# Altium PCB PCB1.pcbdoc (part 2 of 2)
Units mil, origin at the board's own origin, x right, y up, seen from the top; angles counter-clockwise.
Board outline 3270 x 3720 mil, 2 copper layers (Top Layer, Bottom Layer); 54 components, 39 nets, 206 pads, 56 vias.
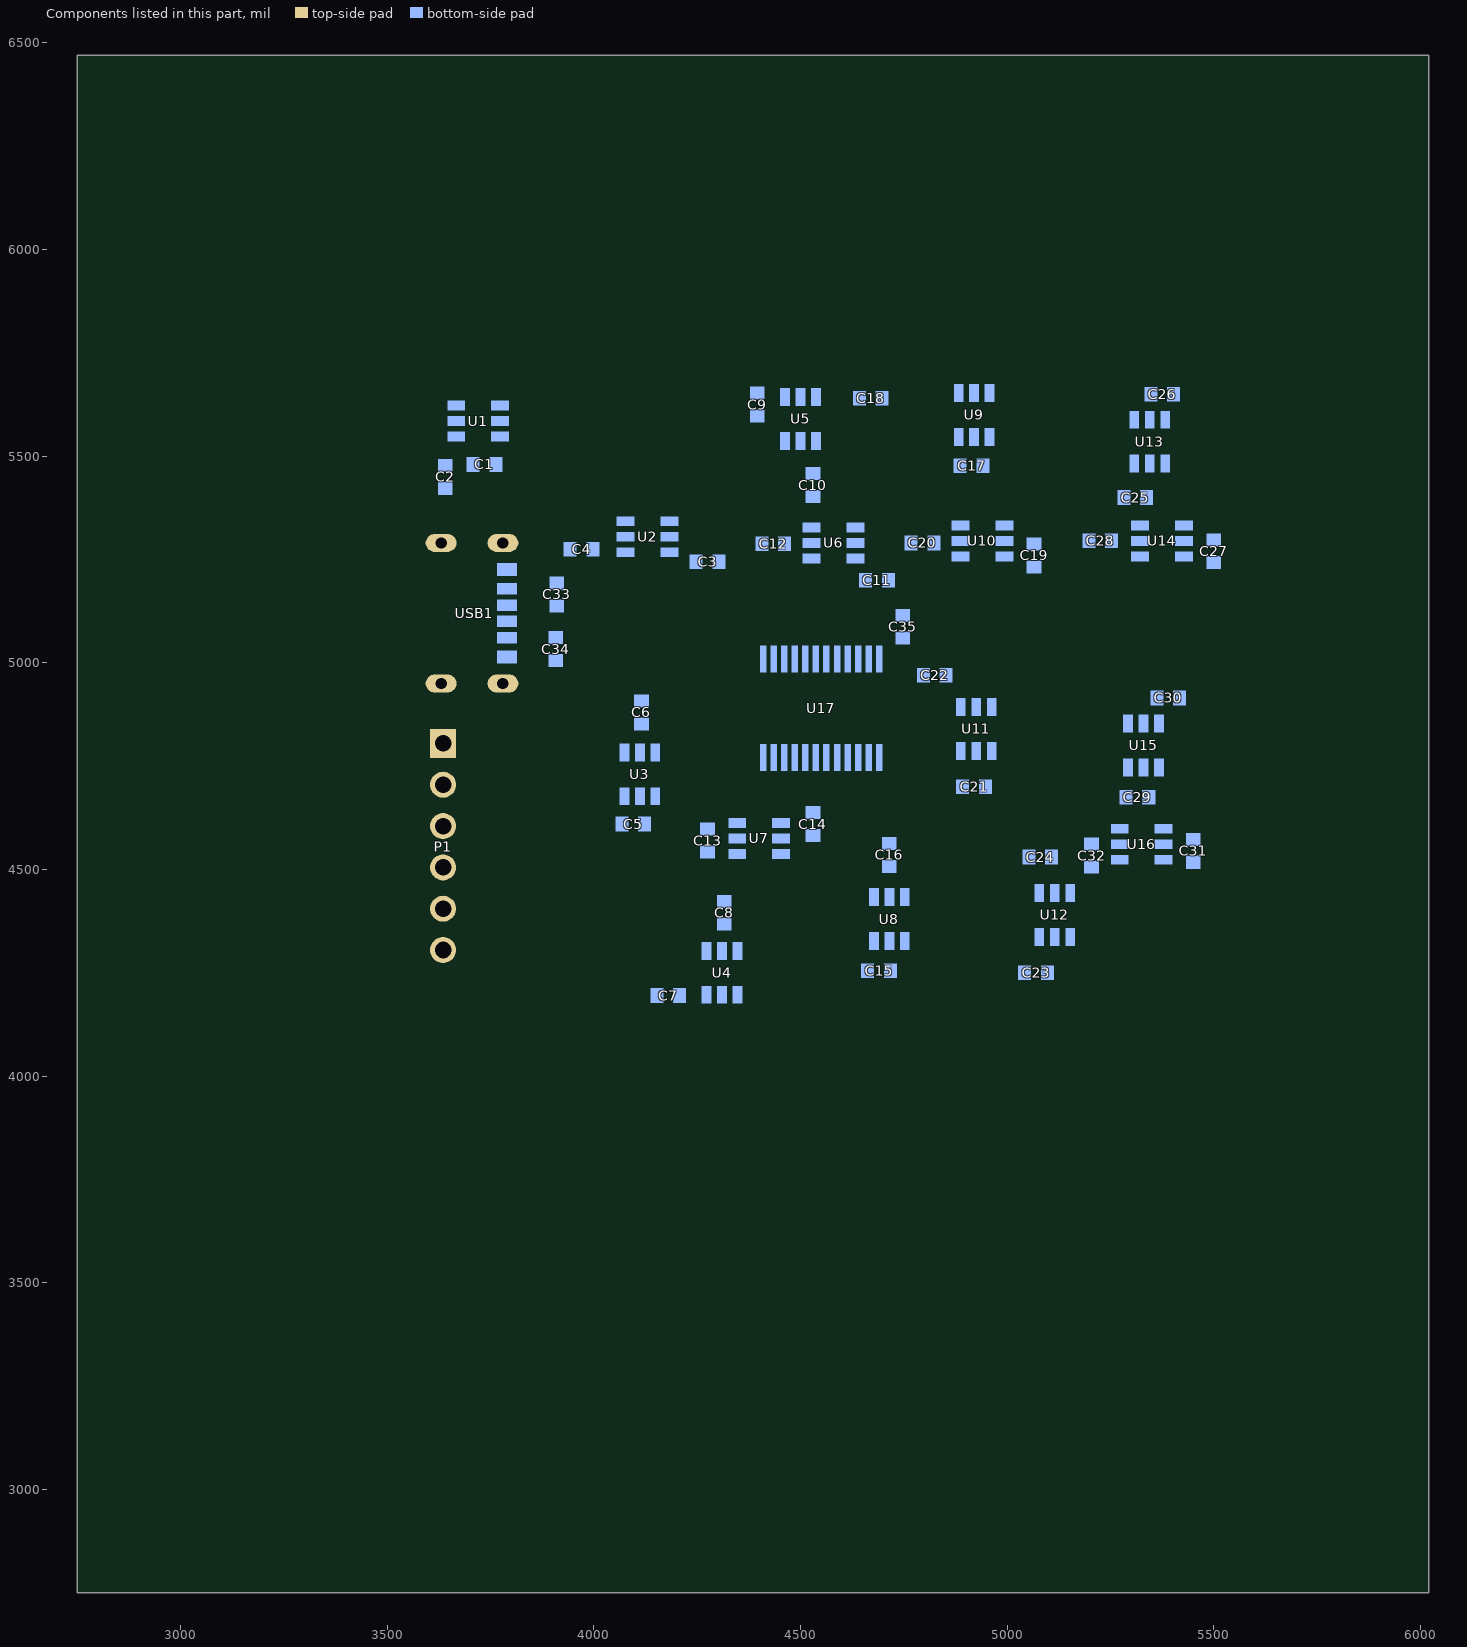
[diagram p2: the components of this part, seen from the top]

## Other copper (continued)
Bottom Layer:
  region net GND: 3702.44,5512.72 3712.44,5512.72 ccw(c3731.19,5512.72) 3719.94,5497.72 3694.94,5497.72 ccw(c3683.69,5512.72)
  region net GND: 3676.69,5472.56 3676.69,5482.56 ccw(c3676.69,5501.31) 3691.69,5490.06 3691.69,5465.06 ccw(c3676.69,5453.81)
  region: 3768.15,5512.72 3778.15,5512.72 ccw(c4490.25,5512.72) 3778.31,5497.72 3760.65,5497.72 ccw(c3749.4,5512.72)
  region: 3754.05,5456.98 3746.46,5463.54 ccw(c3574,5474.49) 3746.81,5474.49 3769.96,5462.28 ccw(c3769.96,5435.77)
  region net GND: 3672.72,5482.56 3672.72,5472.56 ccw(c3672.72,5453.81) 3657.72,5465.06 3657.72,5490.06 ccw(c3672.72,5501.31)
  region net +5V: 3663.02,5406.49 3653.98,5401.39 ccw(c3638.07,5380.18) 3638.07,5406.69 3657.72,5422.4 ccw(c3684.23,5422.4)
  region net +5V: 3616.98,5438.39 3626.02,5443.49 ccw(c3641.93,5464.7) 3641.93,5438.19 3622.28,5422.48 ccw(c3595.77,5422.48)
  region net PAD2: 4226.39,5258.98 4231.49,5268.02 ccw(c4247.4,5289.23) 4247.4,5262.72 4231.69,5243.07 ccw(c4205.18,5243.07)
  region net +5V: 4002.56,5242.28 3992.56,5242.28 ccw(c3973.81,5242.28) 3985.06,5257.28 4010.06,5257.28 ccw(c4021.31,5242.28)
  region net +5V: 4013.51,5298.02 4018.61,5288.98 ccw(c4039.82,5273.07) 4013.31,5273.07 3997.6,5292.72 ccw(c3997.6,5319.23)
  region net GND: 4106.3,4642.72 4116.3,4642.72 ccw(c4135.05,4642.72) 4123.8,4627.72 4106.81,4627.72 ccw(c3888.95,4627.72)
  region net PAD3: 4053.54,4589.02 4046.46,4596.1 ccw(c4025.1,4611.93) 4051.69,4611.93 4067.4,4592.28 ccw(c4067.4,4561.16)
  region net PAD3: 4062.44,4642.72 4072.44,4642.72 ccw(c4091.19,4642.72) 4079.94,4627.72 4054.94,4627.72 ccw(c4043.69,4642.72)
  region net +5V: 4120,4821.69 4110,4821.69 ccw(c4091.25,4821.69) 4102.5,4836.69 4127.5,4836.69 ccw(c4138.75,4821.69)
  region net +5V: 4141.46,4868.54 4138.85,4851.78 ccw(c4154.34,4836.69) 4132.72,4836.69 4132.72,4868.19 ccw(c4136.9,4873.1)
  region net PAD4: 4238.31,4200 4238.31,4190 ccw(c4238.31,4171.25) 4223.31,4182.5 4223.31,4207.5 ccw(c4238.31,4218.75)
  region net PAD4: 4226.46,4213.54 4231.2,4204.13 ccw(c4253.28,4182.05) 4223.31,4190.81 4223.31,4212.72 ccw(c4224.19,4215.81)
  region net +5V: 4320,4336.69 4310,4336.69 ccw(c4291.25,4336.69) 4302.5,4351.69 4327.5,4351.69 ccw(c4338.75,4336.69)
  region net +5V: 4328.98,4388.49 4338.02,4383.39 ccw(c4359.23,4367.48) 4332.72,4367.48 4313.07,4383.19 ccw(c4313.07,4409.7)
  region net PAD5: 4418.02,5581.49 4408.98,5576.39 ccw(c4393.07,5555.18) 4393.07,5581.69 4412.72,5597.4 ccw(c4439.23,5597.4)
  region net PAD5: 4371.98,5613.39 4381.02,5618.49 ccw(c4396.93,5639.7) 4396.93,5613.19 4377.28,5597.48 ccw(c4350.77,5597.48)
  region net +5V: 4553.02,5441.61 4543.98,5436.51 ccw(c4528.07,5415.3) 4528.07,5441.81 4547.72,5457.52 ccw(c4574.23,5457.52)
  region net +5V: 4543.98,5478.61 4553.02,5473.51 ccw(c4574.23,5457.6) 4547.72,5457.6 4528.07,5473.31 ccw(c4528.07,5499.82)
  region net +5V: 4492.4,5293.47 4492.4,5283.47 ccw(c4492.4,5264.72) 4477.4,5275.97 4477.4,5300.97 ccw(c4492.4,5312.22)
  region net GND: 4302.69,4547.44 4302.69,4537.44 ccw(c4302.69,4527.06) 4292.72,4529.94 4292.72,4554.94 ccw(c4302.69,4557.82)
  region net PAD7: 4250,4580 4250,4590 ccw(c4249.78,4597.5) 4257.28,4597.5 4257.28,4581.81 ccw(c4257.28,4566.27)
  region net PAD7: 4307.72,4602.56 4307.72,4592.56 ccw(c4307.72,4573.81) 4292.72,4585.06 4292.72,4610.06 ccw(c4307.72,4621.31)
  region net +5V: 4516.02,4616.51 4506.98,4621.61 ccw(c4485.77,4637.52) 4512.28,4637.52 4531.93,4621.81 ccw(c4531.93,4595.3)
  region net +5V: 4562.72,4642.56 4562.72,4632.56 ccw(c4562.72,4613.81) 4547.72,4625.06 4547.72,4650.06 ccw(c4562.72,4661.31)
  region net PAD8: 4663.16,4231.09 4646.46,4228.54 ccw(c4641.97,4233.03) 4646.69,4237.28 4678.19,4237.28 ccw(c4678.19,4215.96)
  region net PAD8: 4672.6,4287.72 4682.6,4287.72 ccw(c4705.89,4272.72) 4678.19,4272.72 4665.1,4272.72 ccw(c4653.85,4287.72)
  region net +5V: 4720,4476.69 4710,4476.69 ccw(c4691.25,4476.69) 4702.5,4491.69 4727.5,4491.69 ccw(c4738.75,4476.69)
  region net +5V: 4691.98,4523.39 4701.02,4528.49 ccw(c4716.93,4549.7) 4716.93,4523.19 4697.28,4507.48 ccw(c4670.77,4507.48)
  region net +5V: 4681.61,5616.98 4676.51,5626.02 ccw(c4655.3,5641.93) 4681.81,5641.93 4697.52,5622.28 ccw(c4697.52,5595.77)
  region net +5V: 4728.31,5655 4728.31,5645 ccw(c4728.31,5626.25) 4713.31,5637.5 4713.31,5657.72 ccw(c4728.31,5697.77)
  region net PAD10: 5041.98,5248.39 5051.02,5253.49 ccw(c5066.93,5274.7) 5066.93,5248.19 5047.28,5232.48 ccw(c5020.77,5232.48)
  region net PAD10: 5088.91,5233.16 5096.46,5211.46 ccw(c5083.77,5198.77) 5082.72,5216.69 5082.72,5248.19 ccw(c5104.04,5248.19)
  region net +5V: 4814.05,5266.98 4806.46,5273.54 ccw(c4634,5284.49) 4806.81,5284.49 4829.96,5272.28 ccw(c4829.96,5245.77)
  region net +5V: 4853.31,5295 4853.31,5285 ccw(c4853.31,5266.25) 4838.31,5277.5 4838.31,5302.5 ccw(c4853.31,5313.75)
  region net PAD11: 4897.44,4667.28 4887.44,4667.28 ccw(c4868.69,4667.28) 4879.94,4682.28 4904.94,4682.28 ccw(c4916.19,4667.28)
  region net PAD11: 4887.44,4732.72 4897.44,4732.72 ccw(c4916.19,4732.72) 4904.94,4717.72 4879.94,4717.72 ccw(c4868.69,4732.72)
  region net +5V: 4831.51,4983.98 4836.61,4993.02 ccw(c4852.52,5014.23) 4852.52,4987.72 4836.81,4968.07 ccw(c4810.3,4968.07)
  region net +5V: 4883.31,4960 4883.31,4950 ccw(c4868.31,4901.88) 4868.31,4952.28 4868.31,4967.5 ccw(c4883.31,4978.75)
  region net PAD12: 5047.44,4227.44 5037.44,4227.44 ccw(c5029.94,4224.06) 5029.94,4232.28 5054.94,4232.28 ccw(c5054.94,4224.06)
  region net PAD12: 5058.39,4273.02 5063.49,4263.98 ccw(c5084.7,4248.07) 5058.19,4248.07 5042.48,4267.72 ccw(c5042.48,4294.23)
  region net +5V: 5123.51,4553.02 5128.61,4543.98 ccw(c5149.82,4528.07) 5123.31,4528.07 5107.6,4547.72 ccw(c5107.6,4574.23)
  region net +5V: 5128.61,4516.02 5123.51,4506.98 ccw(c5107.6,4485.77) 5107.6,4512.28 5123.31,4531.93 ccw(c5149.82,4531.93)
  region net PAD13: 5298.39,5423.02 5303.49,5413.98 ccw(c5324.7,5398.07) 5298.19,5398.07 5282.48,5417.72 ccw(c5282.48,5444.23)
  region net +5V: 5316.69,5645 5316.69,5655 ccw(c5316.69,5673.75) 5331.69,5662.5 5331.69,5637.5 ccw(c5316.69,5626.25)
  region net +5V: 5350,5617.28 5340,5617.28 ccw(c5321.25,5617.28) 5332.5,5632.28 5357.5,5632.28 ccw(c5368.75,5617.28)
  region net PAD14: 5467.28,5252.6 5467.28,5262.6 ccw(c5482.28,5285.89) 5482.28,5258.19 5482.28,5245.1 ccw(c5467.28,5233.85)
  region net PAD14: 5505,5211.69 5495,5211.69 ccw(c5476.25,5211.69) 5487.5,5226.69 5512.5,5226.69 ccw(c5523.75,5211.69)
  region net +5V: 5247.56,5327.72 5257.56,5327.72 ccw(c5276.31,5327.72) 5265.06,5312.72 5240.06,5312.72 ccw(c5228.81,5327.72)
  region net +5V: 5283.31,5300 5283.31,5290 ccw(c5283.31,5271.25) 5268.31,5282.5 5268.31,5307.5 ccw(c5283.31,5318.75)
  region net PAD15: 5287.6,4707.72 5297.6,4707.72 ccw(c5320.53,4707.72) 5303.19,4692.72 5280.1,4692.72 ccw(c5268.85,4707.72)
  region net +5V: 5346.49,4891.98 5341.39,4901.02 ccw(c5320.18,4916.93) 5346.69,4916.93 5362.4,4897.28 ccw(c5362.4,4870.77)
  region net PAD16: 5417.28,4518.75 5417.28,4528.75 ccw(c5417.28,4556.34) 5432.28,4533.19 5432.28,4511.25 ccw(c5417.28,4500)
  region net PAD16: 5473.02,4501.49 5463.98,4496.39 ccw(c5448.07,4475.18) 5448.07,4501.69 5467.72,4517.4 ccw(c5494.23,4517.4)
  region net +5V: 5171.5,4556.15 5171.5,4566.15 ccw(c5171.5,4584.9) 5186.5,4573.65 5186.5,4548.65 ccw(c5171.5,4537.4)
  region net +5V: 5236.94,4566.15 5236.94,4556.15 ccw(c5236.94,4537.4) 5221.94,4548.65 5221.94,4573.65 ccw(c5236.94,4584.9)
  region net +5V: 3877.07,5133.05 3877.07,5143.05 ccw(c3877.07,5161.8) 3892.07,5150.55 3892.07,5125.55 ccw(c3877.07,5114.3)
  region net +5V: 3914.79,5107.3 3904.79,5107.3 ccw(c3886.04,5107.3) 3897.29,5122.3 3922.29,5122.3 ccw(c3933.54,5107.3)
  region net +5V: 3923.77,5159.1 3932.81,5154 ccw(c3954.02,5138.09) 3927.5,5138.09 3907.86,5153.8 ccw(c3907.86,5180.31)
  region net +5V: 3904.79,5091.48 3914.79,5091.48 ccw(c3933.54,5091.48) 3922.29,5076.48 3897.29,5076.48 ccw(c3886.04,5091.48)
  region net +5V: 4750,5040 4740,5040 ccw(c4732.5,5035.48) 4732.5,5044.23 4757.5,5044.23 ccw(c4757.5,5035.48)
  region net S3: 3601.03,4431.9 3608.1,4438.97 3609.88,4437.34 3611.58,4436.08 3613.2,4435.17 3614.76,4434.55 3616.3,4434.2 3617.82,4434.07 3619.35,4434.13 3620.91,4434.32 3627.82,4435.79 3631.95,4436.38 3634.26,4436.49 3636.75,4436.45 3603.55,4403.25 3603.51,4405.74 3603.62,4408.05 3604.21,4412.18 3605.68,4419.09 3605.87,4420.65 3605.93,4422.18 3605.8,4423.7 3605.45,4425.24 3604.83,4426.8 3603.92,4428.42 3602.66,4430.12
  region net S2: 3601.03,4531.9 3608.1,4538.97 3609.88,4537.34 3611.58,4536.08 3613.2,4535.17 3614.76,4534.55 3616.3,4534.2 3617.82,4534.07 3619.35,4534.13 3620.91,4534.32 3627.82,4535.79 3631.95,4536.38 3634.26,4536.49 3636.75,4536.45 3603.55,4503.25 3603.51,4505.74 3603.62,4508.05 3604.21,4512.18 3605.68,4519.09 3605.87,4520.65 3605.93,4522.18 3605.8,4523.7 3605.45,4525.24 3604.83,4526.8 3603.92,4528.42 3602.66,4530.12
  region net S1: 3678.04,4610 3678.04,4600 3675.63,4599.89 3673.54,4599.59 3671.75,4599.09 3670.21,4598.41 3668.87,4597.58 3667.7,4596.59 3666.66,4595.47 3665.7,4594.23 3661.85,4588.31 3659.34,4584.97 3657.79,4583.25 3656,4581.52 3656,4628.48 3657.79,4626.75 3659.34,4625.03 3661.85,4621.69 3665.7,4615.77 3666.66,4614.53 3667.7,4613.41 3668.87,4612.42 3670.21,4611.59 3671.75,4610.91 3673.54,4610.41 3675.63,4610.11
  region net S0: 3678.04,4710 3678.04,4700 3675.63,4699.89 3673.54,4699.59 3671.75,4699.09 3670.21,4698.41 3668.87,4697.58 3667.7,4696.59 3666.66,4695.47 3665.7,4694.23 3661.85,4688.31 3659.34,4684.97 3657.79,4683.25 3656,4681.52 3656,4728.48 3657.79,4726.75 3659.34,4725.03 3661.85,4721.69 3665.7,4715.77 3666.66,4714.53 3667.7,4713.41 3668.87,4712.42 3670.21,4711.59 3671.75,4710.91 3673.54,4710.41 3675.63,4710.11
  region: 3778.15,5520.79 3768.15,5520.79 ccw(c3749.4,5520.79) 3760.65,5535.79 3785.65,5535.79 ccw(c3796.9,5520.79)
  region net GND: 3736.5,5580 3736.5,5590 ccw(c3736.5,5609.92) 3751.5,5596.81 3751.5,5573.19 ccw(c3736.5,5560.08)
  region net T1: 3809.8,5627.4 3809.8,5617.4 ccw(c3809.8,5597.48) 3794.8,5610.59 3794.8,5634.21 ccw(c3809.8,5647.32)
  region net +5V: 3639.96,5567.89 3639.36,5581.43 ccw(c3622.01,5596.81) 3645.2,5596.81 3655.87,5573.19 ccw(c3655.87,5546.67)
  region net PAD2: 4207.6,5272.6 4207.6,5262.6 ccw(c4214.5,5255.79) 4204.8,5255.79 4204.8,5279.41 ccw(c4214.5,5279.41)
  region net T2: 4155,5337.4 4155,5347.4 ccw(c4154.68,5354.21) 4161.5,5354.21 4161.5,5330.59 ccw(c4154.68,5330.59)
  region net +5V: 4040.2,5300 4040.2,5310 ccw(c4040.2,5329.92) 4055.2,5316.81 4055.2,5293.19 ccw(c4040.2,5280.08)
  region net PAD3: 4072.44,4640.41 4062.44,4640.41 ccw(c3746.25,4640.41) 4062.08,4655.41 4079.94,4655.41 ccw(c4091.19,4640.41)
  region net GND: 4116.3,4640.41 4106.3,4640.41 ccw(c4086.37,4640.41) 4099.48,4655.41 4123.11,4655.41 ccw(c4136.22,4640.41)
  region net T3: 4168.4,4664.43 4172.22,4646.46 ccw(c4133.02,4607.26) 4160.51,4655.41 4160.51,4677.75 ccw(c4190.48,4686.51)
  region net +5V: 4110,4820.02 4120,4820.02 ccw(c4157.77,4820.02) 4123.11,4805.02 4102.5,4805.02 ccw(c4091.25,4820.02)
  region net PAD4: 4245.79,4190 4245.79,4200 ccw(c4245.79,4218.75) 4260.79,4207.5 4260.79,4182.5 ccw(c4245.79,4171.25)
  region net T4: 4366.46,4222.99 4367.1,4209.48 ccw(c4389.18,4187.4) 4359.21,4196.16 4359.21,4218.5 ccw(c4353.35,4236.1)
  region net +5V: 4310,4339.8 4320,4339.8 ccw(c4383.03,4339.8) 4321.81,4324.8 4302.5,4324.8 ccw(c4291.25,4339.8)
  region net PAD5: 4442.9,5542.47 4437.47,5562.04 ccw(c4459.55,5584.12) 4450.79,5554.15 4450.79,5529.15 ccw(c4420.82,5520.39)
  region net GND: 4505,5573.5 4515,5573.5 ccw(c4548.68,5558.5) 4511.81,5558.5 4497.5,5558.5 ccw(c4486.25,5573.5)
  region net T5: 4529.11,5509.89 4520.29,5515.21 ccw(c4499.07,5531.12) 4525.59,5531.12 4545.02,5515.2 ccw(c4545.02,5488.68)
  region net +5V: 4517.11,5619.96 4506.74,5616.19 ccw(c4490.83,5594.98) 4490.83,5621.5 4511.81,5635.87 ccw(c4538.33,5635.87)
  region net PAD6: 4660.98,5231.85 4645.78,5232.9 ccw(c4623.7,5210.82) 4632.46,5240.79 4654.8,5240.79 ccw(c4682.28,5253.15)
  region net PAD6: 4656.46,5263.54 4661.94,5254.87 ccw(c4679.88,5236.93) 4654.8,5240.79 4654.8,5264.41 ccw(c4655.86,5264.41)
  region net GND: 4655,5295 4655,5285 ccw(c4772.94,5278.19) 4654.8,5278.19 4654.8,5301.81 ccw(c4772.94,5301.81)
  region net T6: 4598.88,5306.99 4603.62,5325.87 ccw(c4581.67,5347.83) 4611.5,5339.21 4611.5,5315.59 ccw(c4627.9,5277.97)
  region net +5V: 4490.2,5283.47 4490.2,5293.47 ccw(c4490.2,5312.22) 4505.2,5300.97 4505.2,5278.19 ccw(c4490.2,5259.53)
  region net T7: 4372.6,4542.6 4372.6,4532.6 ccw(c4376.21,4525.79) 4368.5,4525.79 4368.5,4549.41 ccw(c4376.21,4549.41)
  region net +5V: 4477.48,4592.11 4480.11,4580.6 ccw(c4501.32,4564.69) 4474.8,4564.69 4461.57,4586.81 ccw(c4461.57,4613.33)
  region net PAD8: 4682.6,4290.2 4672.6,4290.2 ccw(c4652.68,4290.2) 4665.79,4305.2 4689.41,4305.2 ccw(c4702.52,4290.2)
  region net T8: 4776.2,4357.72 4772.1,4339.48 ccw(c4794.18,4317.4) 4764.21,4326.16 4764.21,4348.5 ccw(c4734.92,4399.01)
  region net +5V: 4710,4469.8 4720,4469.8 ccw(c4739.92,4469.8) 4726.81,4454.8 4703.19,4454.8 ccw(c4690.08,4469.8)
  region net PAD9: 4891.4,5510.2 4881.4,5510.2 ccw(c4862.65,5510.2) 4873.9,5525.2 4894.41,5525.2 ccw(c4930.29,5510.2)
  region net PAD9: 4880,5580 4890,5580 ccw(c4907.19,5580) 4894.41,5568.5 4872.5,5568.5 ccw(c4867.44,5580)
  region net T9: 4949.11,5519.89 4940.29,5525.21 ccw(c4919.07,5541.12) 4945.59,5541.12 4965.02,5525.2 ccw(c4965.02,5498.68)
  region net +5V: 4911.71,5626.19 4902.89,5631.51 ccw(c4881.67,5647.42) 4908.19,5647.42 4927.62,5631.5 ccw(c4927.62,5604.98)
  region net PAD10: 5029.8,5262.6 5029.8,5252.6 ccw(c5029.8,5232.68) 5014.8,5245.79 5014.8,5269.41 ccw(c5029.8,5282.52)
  region net +5V: 4850.2,5285 4850.2,5295 ccw(c4850.2,5313.75) 4865.2,5302.5 4865.2,5283.19 ccw(c4850.2,5221.97)
  region net PAD11: 4897.44,4750.2 4887.44,4750.2 ccw(c4868.69,4750.2) 4879.94,4765.2 4899.41,4765.2 ccw(c4955.5,4750.2)
  region net T11: 4955,4815 4965,4815 ccw(c4972.5,4816.08) 4972.5,4808.5 4950.59,4808.5 ccw(c4948.01,4815)
  region net +5V: 4930,4865 4920,4865 ccw(c4913.19,4864.68) 4913.19,4871.5 4936.81,4871.5 ccw(c4936.81,4864.68)
  region net +5V: 4920,4920 4930,4920 ccw(c4936.81,4921.87) 4936.81,4914.8 4913.19,4914.8 ccw(c4913.19,4921.87)
  region net PAD12: 5082.6,4300.2 5072.6,4300.2 ccw(c5052.68,4300.2) 5065.79,4315.2 5089.41,4315.2 ccw(c5102.52,4300.2)
  region net T12: 5131.9,4371.03 5150.78,4366.29 ccw(c5172.13,4387.63) 5164.21,4358.5 5140.59,4358.5 ccw(c5101.62,4340.74)
  region net PAD13: 5312.6,5445.2 5302.6,5445.2 ccw(c5282.68,5445.2) 5295.79,5460.2 5319.41,5460.2 ccw(c5332.52,5445.2)
  region net PAD13: 5305,5518.5 5315,5518.5 ccw(c5342.71,5518.5) 5319.41,5503.5 5297.5,5503.5 ccw(c5286.25,5518.5)
  region net T13: 5387.4,5445.2 5377.4,5445.2 ccw(c5357.48,5445.2) 5370.59,5460.2 5394.21,5460.2 ccw(c5407.32,5445.2)
  region net +5V: 5340,5624.8 5350,5624.8 ccw(c5369.92,5624.8) 5356.81,5609.8 5333.19,5609.8 ccw(c5320.08,5624.8)
  region net PAD14: 5464.8,5262.6 5464.8,5252.6 ccw(c5464.8,5232.68) 5449.8,5245.79 5449.8,5269.41 ccw(c5464.8,5282.52)
  region net T14: 5401.42,5327.4 5401.42,5337.4 ccw(c5399.39,5344.21) 5406.5,5344.21 5406.5,5320.59 ccw(c5399.39,5320.59)
  region net +5V: 5285.2,5290 5285.2,5300 ccw(c5285.2,5319.92) 5300.2,5306.81 5300.2,5283.19 ccw(c5285.2,5270.08)
  region net PAD15: 5297.6,4710.2 5287.6,4710.2 ccw(c5267.68,4710.2) 5280.79,4725.2 5304.41,4725.2 ccw(c5317.52,4710.2)
  region net PAD15: 5287.6,4772.6 5297.6,4772.6 ccw(c5304.41,4776.21) 5304.41,4768.5 5280.79,4768.5 ccw(c5280.79,4776.21)
  region net +5V: 5325,4882.56 5335,4882.56 ccw(c5342.82,4882.56) 5341.81,4874.8 5318.19,4874.8 ccw(c5317.18,4882.56)
  region net +5V: 5347.11,4831.51 5338.29,4826.19 ccw(c5322.38,4804.98) 5322.38,4831.5 5341.81,4847.42 ccw(c5368.33,4847.42)
  region net PAD16: 5415.34,4528.75 5415.34,4518.75 ccw(c5415.34,4498.83) 5400.34,4511.94 5400.34,4535.56 ccw(c5415.34,4548.68)
  region net +5V: 5235.73,4556.15 5235.73,4566.15 ccw(c5235.73,4586.08) 5250.73,4572.96 5250.73,4549.34 ccw(c5235.73,4536.23)
  region net +5V: 5296.2,4578.27 5299.34,4567.27 ccw(c5320.56,4551.36) 5294.04,4551.36 5280.29,4572.96 ccw(c5280.29,4599.48)
  region net T8: 4567.79,4723.52 4557.79,4723.52 ccw(c4517.21,4723.52) 4554.92,4738.52 4570.66,4738.52 ccw(c4608.37,4723.52)
  region net T12: 4593.38,4723.52 4583.38,4723.52 ccw(c4542.8,4723.52) 4580.51,4738.52 4596.25,4738.52 ccw(c4633.96,4723.52)
  region net T16: 4618.97,4723.52 4608.97,4723.52 ccw(c4568.39,4723.52) 4606.1,4738.52 4621.84,4738.52 ccw(c4659.55,4723.52)
  region net T15: 4644.56,4723.52 4634.56,4723.52 ccw(c4593.98,4723.52) 4631.69,4738.52 4647.43,4738.52 ccw(c4685.14,4723.52)
  region net T11: 4670,4723.52 4660,4723.52 ccw(c4617.34,4723.52) 4657.28,4738.52 4673.02,4738.52 ccw(c4708.71,4723.52)
  region net OUT: 4685.74,4818.48 4695.74,4818.48 ccw(c4736.32,4818.48) 4698.61,4803.48 4682.87,4803.48 ccw(c4645.16,4818.48)
  region net T4: 4540,4723.52 4530,4723.52 ccw(c4360.24,4723.52) 4529.34,4738.52 4545.08,4738.52 ccw(c4564.67,4723.52)
  region net T3: 4491.02,4736.02 4481.02,4736.02 ccw(c4478.15,4735.62) 4478.15,4738.52 4493.89,4738.52 ccw(c4493.89,4735.62)
  region net T9: 4583.38,5056.48 4593.38,5056.48 ccw(c4633.96,5056.48) 4596.25,5041.48 4580.51,5041.48 ccw(c4542.8,5056.48)
  region net T10: 4608.97,5056.48 4618.97,5056.48 ccw(c4659.55,5056.48) 4621.84,5041.48 4606.1,5041.48 ccw(c4568.39,5056.48)
  region net T13: 4634.56,5056.48 4644.56,5056.48 ccw(c4685.14,5056.48) 4647.43,5041.48 4631.69,5041.48 ccw(c4593.98,5056.48)
  region net T14: 4660.15,5054.85 4670.15,5054.85 ccw(c4702.68,5054.85) 4673.02,5041.48 4657.28,5041.48 ccw(c4627.62,5054.85)
  region net +5V: 4685.74,5045.74 4695.74,5045.74 ccw(c4700.33,5045.74) 4698.61,5041.48 4682.87,5041.48 ccw(c4681.15,5045.74)
  region net T6: 4557.79,5056.48 4567.79,5056.48 ccw(c4608.37,5056.48) 4570.66,5041.48 4554.92,5041.48 ccw(c4517.21,5056.48)
  region net S3: 4414.26,4964.26 4404.26,4964.26 ccw(c4376.68,4964.26) 4401.39,4976.52 4417.13,4976.52 ccw(c4441.84,4964.26)
  region net S2: 4439.84,4961.52 4429.84,4961.52 ccw(c4389.26,4961.52) 4426.97,4976.52 4442.71,4976.52 ccw(c4480.42,4961.52)
  region net GND: 4465.43,4961.52 4455.43,4961.52 ccw(c4414.85,4961.52) 4452.56,4976.52 4468.3,4976.52 ccw(c4506.01,4961.52)
  region net T5: 4532.21,5052.79 4542.21,5052.79 ccw(c4565.9,5052.79) 4545.08,5041.48 4529.34,5041.48 ccw(c4508.52,5052.79)
  region net +5V: 3825,5065 3825,5055 ccw(c3825,5042.2) 3813.35,5047.5 3813.35,5072.5 ccw(c3825,5077.8)
  region net +5V: 3825.95,5184.06 3825.95,5174.06 ccw(c3825.95,5159.72) 3813.35,5166.56 3813.35,5191.56 ccw(c3825.95,5198.39)
  region net +5V: 3765.95,5174.06 3765.95,5184.06 ccw(c3588.02,5191.56) 3766.1,5191.56 3766.1,5166.56 ccw(c3588.02,5166.56)
  region: 3758.07,5475.14 3765.14,5468.07 3764.41,5467.21 3763.79,5466.24 3762.84,5464.02 3762.26,5461.65 3761.99,5459.33 3749.33,5471.99 3751.65,5472.26 3754.02,5472.84 3756.24,5473.79 3757.21,5474.41
  region net PAD2: 4199.19,5262.6 4194.7,5272.6 4197.59,5272.69 4198.94,5272.86 4200.17,5273.18 4201.24,5273.67 4202.12,5274.39 4202.75,5275.37 4203.11,5276.66 4214.3,5263.01 4210.38,5263.09 4206.75,5262.93 4203.11,5262.71
  region net PAD3: 4045,4592.56 4055,4592.56 4055.09,4591.6 4055.34,4590.91 4055.73,4590.4 4056.23,4590 4057.5,4589.23 4058.21,4588.71 4058.95,4588.01 4041.05,4588.01 4041.79,4588.71 4042.5,4589.23 4043.77,4590 4044.27,4590.4 4044.66,4590.91 4044.91,4591.6
  region net PAD4: 4221.93,4194.86 4214.86,4201.93 4215.59,4202.79 4216.21,4203.76 4217.16,4205.98 4217.74,4208.35 4218.01,4210.67 4230.67,4198.01 4228.35,4197.74 4225.98,4197.16 4223.76,4196.21 4222.79,4195.59
  region net PAD5: 4336.41,5660 4336.41,5650 4335.29,5649.91 4334.16,5649.66 4331.93,5648.77 4329.83,5647.5 4328.01,5646.05 4328.01,5663.95 4329.83,5662.5 4331.93,5661.23 4334.16,5660.34 4335.29,5660.09
  region net PAD7: 4262.44,4590 4262.44,4580 4261.49,4579.91 4260.81,4579.66 4260.32,4579.27 4259.94,4578.77 4259.21,4577.5 4258.71,4576.79 4258.01,4576.05 4258.01,4593.95 4258.71,4593.21 4259.21,4592.5 4259.94,4591.23 4260.32,4590.73 4260.81,4590.34 4261.49,4590.09
  region net PAD8: 4658.07,4240.14 4665.14,4233.07 4664.41,4232.21 4663.79,4231.24 4662.84,4229.02 4662.26,4226.65 4661.99,4224.33 4649.33,4236.99 4651.65,4237.26 4654.02,4237.84 4656.24,4238.79 4657.21,4239.41
  region net PAD9: 4888.54,5576.46 4881.46,5583.54 4882.13,5584.32 4882.57,5585.12 4882.83,5585.93 4882.96,5586.78 4883.01,5590.67 4895.67,5578.01 4891.78,5577.96 4890.93,5577.83 4890.12,5577.57 4889.32,5577.13
  region net PAD10: 5084.86,5223.07 5091.93,5230.14 5092.79,5229.41 5093.76,5228.79 5095.98,5227.84 5098.35,5227.26 5100.67,5226.99 5088.01,5214.33 5087.74,5216.65 5087.16,5219.02 5086.21,5221.24 5085.59,5222.21
  region net PAD11: 4887.44,4676.41 4897.44,4676.41 4897.53,4675.29 4897.78,4674.16 4898.67,4671.93 4899.94,4669.83 4901.39,4668.01 4883.49,4668.01 4884.94,4669.83 4886.21,4671.93 4887.1,4674.16 4887.35,4675.29
  region net PAD12: 5028.07,4220.14 5035.14,4213.07 5034.41,4212.21 5033.79,4211.24 5032.84,4209.02 5032.26,4206.65 5031.99,4204.33 5019.33,4216.99 5021.65,4217.26 5024.02,4217.84 5026.24,4218.79 5027.21,4219.41
  region net PAD13: 5315,5503.59 5305,5503.59 5304.91,5504.71 5304.66,5505.84 5303.77,5508.07 5302.5,5510.17 5301.05,5511.99 5318.95,5511.99 5317.5,5510.17 5316.23,5508.07 5315.34,5505.84 5315.09,5504.71
  region net PAD14: 5495,5216.41 5505,5216.41 5505.09,5215.29 5505.34,5214.16 5506.23,5211.93 5507.5,5209.83 5508.95,5208.01 5491.05,5208.01 5492.5,5209.83 5493.77,5211.93 5494.66,5214.16 5494.91,5215.29
  region net PAD15: 5306.93,4779.86 5299.86,4786.93 5300.59,4787.79 5301.21,4788.76 5302.16,4790.98 5302.74,4793.35 5303.01,4795.67 5315.67,4783.01 5313.35,4782.74 5310.98,4782.16 5308.76,4781.21 5307.79,4780.59
  region net PAD16: 5464.6,4495.77 5469.76,4504.75 5470.62,4504.03 5471.64,4503.41 5474,4502.48 5476.51,4501.99 5478.85,4501.95 5468.25,4487.53 5467.72,4489.75 5466.98,4491.95 5465.97,4494.01
  region net +5V: 4035.22,5300 4029.7,5310 4030.87,5309.89 4031.95,5309.59 4033.94,5308.62 4035.91,5307.49 4036.96,5306.99 4038.1,5306.6 4043.62,5303.36 4044.35,5302.28 4044.41,5301.84 4044.28,5301.46 4043.54,5300.87 4042.3,5300.46 4040.7,5300.2 4038.88,5300.07
  region net +5V: 4024.02,5301.46 4031.1,5308.54 4031.85,5307.88 4032.57,5307.46 4033.98,5307.09 4035.54,5306.99 4037.47,5306.75 4023.05,5296.15 4023.4,5297.44 4023.97,5298.96 4024.32,5300.41 4024.28,5301
  region net +5V: 4818.07,5285.14 4825.14,5278.07 4824.41,5277.21 4823.79,5276.24 4822.84,5274.02 4822.26,5271.65 4821.99,5269.33 4809.33,5281.99 4811.65,5282.26 4814.02,5282.84 4816.24,5283.79 4817.21,5284.41
  region net +5V: 4740,5056.41 4750,5056.41 4750.09,5055.29 4750.34,5054.16 4751.23,5051.93 4752.5,5049.83 4753.95,5048.01 4736.05,5048.01 4737.5,5049.83 4738.77,5051.93 4739.66,5054.16 4739.91,5055.29
  region net +5V: 4920,4881.41 4930,4881.41 4930.09,4880.29 4930.34,4879.16 4931.23,4876.93 4932.5,4874.83 4933.95,4873.01 4916.05,4873.01 4917.5,4874.83 4918.77,4876.93 4919.66,4879.16 4919.91,4880.29
  region net +5V: 5135,4493.59 5125,4493.59 5124.91,4494.71 5124.66,4495.84 5123.77,4498.07 5122.5,4500.17 5121.05,4501.99 5138.95,4501.99 5137.5,4500.17 5136.23,4498.07 5135.34,4495.84 5135.09,4494.71
  region net +5V: 5114.61,4515.88 5119.86,4524.77 5120.72,4524.05 5121.74,4523.43 5124.09,4522.5 5126.59,4522 5128.94,4521.96 5118.23,4507.62 5117.71,4509.84 5116.99,4512.05 5115.98,4514.11
  region net +5V: 4136.93,4849.86 4129.86,4856.93 4130.59,4857.79 4131.21,4858.76 4132.16,4860.98 4132.74,4863.35 4133.01,4865.67 4145.67,4853.01 4143.35,4852.74 4140.98,4852.16 4138.76,4851.21 4137.79,4850.59
  region net +5V: 4370,4453.59 4360,4453.59 4359.91,4454.71 4359.66,4455.84 4358.77,4458.07 4357.5,4460.17 4356.05,4461.99 4373.95,4461.99 4372.5,4460.17 4371.23,4458.07 4370.34,4455.84 4370.09,4454.71
  region net GND: 4644.86,4938.07 4651.93,4945.14 4652.79,4944.41 4653.76,4943.79 4655.98,4942.84 4658.35,4942.26 4660.67,4941.99 4648.01,4929.33 4647.74,4931.65 4647.16,4934.02 4646.21,4936.24 4645.59,4937.21
  region net GND: 4611.41,5365 4611.41,5355 4610.29,5354.91 4609.16,5354.66 4606.93,5353.77 4604.83,5352.5 4603.01,5351.05 4603.01,5368.95 4604.83,5367.5 4606.93,5366.23 4609.16,5365.34 4610.29,5365.09
  region net GND: 4515,5558.59 4505,5558.59 4504.91,5559.71 4504.66,5560.84 4503.77,5563.07 4502.5,5565.17 4501.05,5566.99 4518.95,5566.99 4517.5,5565.17 4516.23,5563.07 4515.34,5560.84 4515.09,5559.71
  region net GND: 4945,5583.59 4935,5583.59 4934.91,5584.71 4934.66,5585.84 4933.77,5588.07 4932.5,5590.17 4931.05,5591.99 4948.95,5591.99 4947.5,5590.17 4946.23,5588.07 4945.34,5585.84 4945.09,5584.71
  region net +5V: 3852.5,5115.43 cw(c3893.21,5115.43) 3859.57,5138.36 3847.5,5157.5 3835.43,5162.5 cw(c3741.79,5125.43) 3842.5,5125.43
  region net +5V: 4548.79,5588.28 ccw(c4588.29,5627.79) 4570,5575 4575,5555 4570,5542.93 ccw(c4477.57,5502.93) 4548.79,5574.14
  region net +5V: 4006.35,5276.72 cw(c4065.93,5217.14) 4031.46,5294.02 4039.89,5296.53 4069.36,5300 4057.56,5310 4026.58,5309.9
  region net +5V: 5205,5432.07 cw(c5132.57,5432.07) 5183.79,5380.86 5188.79,5371.72 cw(c5210,5350.5) 5231.21,5371.72 5236.21,5380.86 cw(c5287.43,5432.07) 5215,5432.07
  region net +5V: 4635,4575 ccw(c4628.37,4577.14) 4633.3,4582.07 4652.44,4570 4657.44,4557.93 ccw(c4635,4525.86) 4635,4565

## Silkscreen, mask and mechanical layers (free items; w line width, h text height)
Top Silkscreen Layer:
  text "5" at 4415,5450 h120
  text "1" at 4015,5440 h120
  text "9" at 4820,5425 h120
  text "13" at 5210,5420 h120
  text "2" at 4235,5055 h120
  text "6" at 4625,5055 h120
  text "10" at 5010,5050 h120
  text "14" at 5415,5015 h120
  text "0 1 2 3 G" at 3676.97,4725 h85 r270
  text "7" at 4415,4680 h120
  text "11" at 4825,4670 h120
  text "3" at 4010,4660 h120
  text "15" at 5219.75,4626.4 h120
  text "4" at 4220,4320 h120
  text "8" at 4620,4305 h120
  text "12" at 5010,4295 h120
  text "16" at 5410,4245 h120
Bottom Silkscreen Layer:
  text "仙人掌工作室#3 /  电容触摸方案验证 /  高速扫描一阶段验证板" at 5485,5005 h70.87
Top Solder Mask Layer:
  region: 3977.24,5495 ccw(c3930,5494.56) 3882.76,5495 ccw(c3930,5495.44)
  region: 4388.82,5495 ccw(c4341.57,5495) 4294.33,5495 ccw(c4341.57,5495)
  region: 4790.39,5495 ccw(c4743.15,5494.54) 4695.91,5495 ccw(c4743.15,5495.46)
  region: 5201.97,5495 ccw(c5154.72,5495) 5107.48,5495 ccw(c5154.72,5495)
  region: 4177.24,5115 ccw(c4130,5114.56) 4082.76,5115 ccw(c4130,5115.44)
  region: 4588.82,5120 ccw(c4541.57,5120) 4494.33,5120 ccw(c4541.57,5120)
  region: 4990.39,5110 ccw(c4943.15,5109.54) 4895.91,5110 ccw(c4943.15,5110.46)
  region: 5401.97,5115 ccw(c5354.72,5115) 5307.48,5115 ccw(c5354.72,5115)
  region: 3977.24,4740 ccw(c3930,4739.56) 3882.76,4740 ccw(c3930,4740.44)
  region: 4388.82,4735 ccw(c4341.57,4735) 4294.33,4735 ccw(c4341.57,4735)
  region: 4790.39,4745 ccw(c4743.15,4744.54) 4695.91,4745 ccw(c4743.15,4745.46)
  region: 5201.97,4740 ccw(c5154.72,4740) 5107.48,4740 ccw(c5154.72,4740)
  region: 4177.24,4360 ccw(c4130,4359.56) 4082.76,4360 ccw(c4130,4360.44)
  region: 4588.82,4360 ccw(c4541.57,4360) 4494.33,4360 ccw(c4541.57,4360)
  region: 4990.39,4360 ccw(c4943.15,4359.54) 4895.91,4360 ccw(c4943.15,4360.46)
  region: 5401.97,4360 ccw(c5354.72,4360) 5307.48,4360 ccw(c5354.72,4360)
